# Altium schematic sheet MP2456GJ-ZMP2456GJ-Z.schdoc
size 127 x 101 mm
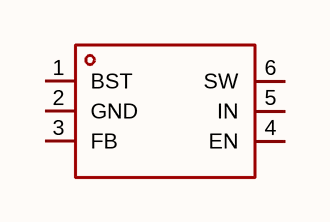
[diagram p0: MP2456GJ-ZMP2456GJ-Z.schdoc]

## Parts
U?  mp2456gj-z  [TSOT-23-6_L2.9-W1.6-P0.95-LS2.8-BR]  (value not drawn)

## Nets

Not connected (* = marked no-connect by the designer): U? 1(BST) 2(GND) 3(FB) 4(EN) 5(IN) 6(SW)

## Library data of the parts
U? = mp2456gj-z: 功能类型:降压型;工作电压:4.5V~50V;输出电压:810mV~45V;输出电流:500mA;输出类型:可调;; Manufacturer: MPS(芯源); AddInBom: yes; ModelId: 2c4039b5b88644c1bda4b4ba9e971667; ModelName: TSOT-23-6_L2.9-W1.6-H1.1-LS2.8-P0.95; ModelTransform: 110.45568,114.173,0,180,0,0,-0.005,-0.0005,0; Function: 降压型; Output Current: 500mA; Frequency - Switching: 1.2MHz; Synchronous Rectifier: 否; Number of Outputs: 1; Topology: 降压式; Quiescent Current: 730uA; Switch tube (built-in/external): 内置; Output Type: 可调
